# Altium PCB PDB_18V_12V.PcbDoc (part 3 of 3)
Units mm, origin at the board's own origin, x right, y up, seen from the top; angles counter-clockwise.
Board outline 185 x 160 mm, 4 copper layers (Top Layer, Int1 (GND), Int2 (GND), Bottom Layer), stack 1.636 mm thick; 209 components, 100 nets, 653 pads, 1413 vias.
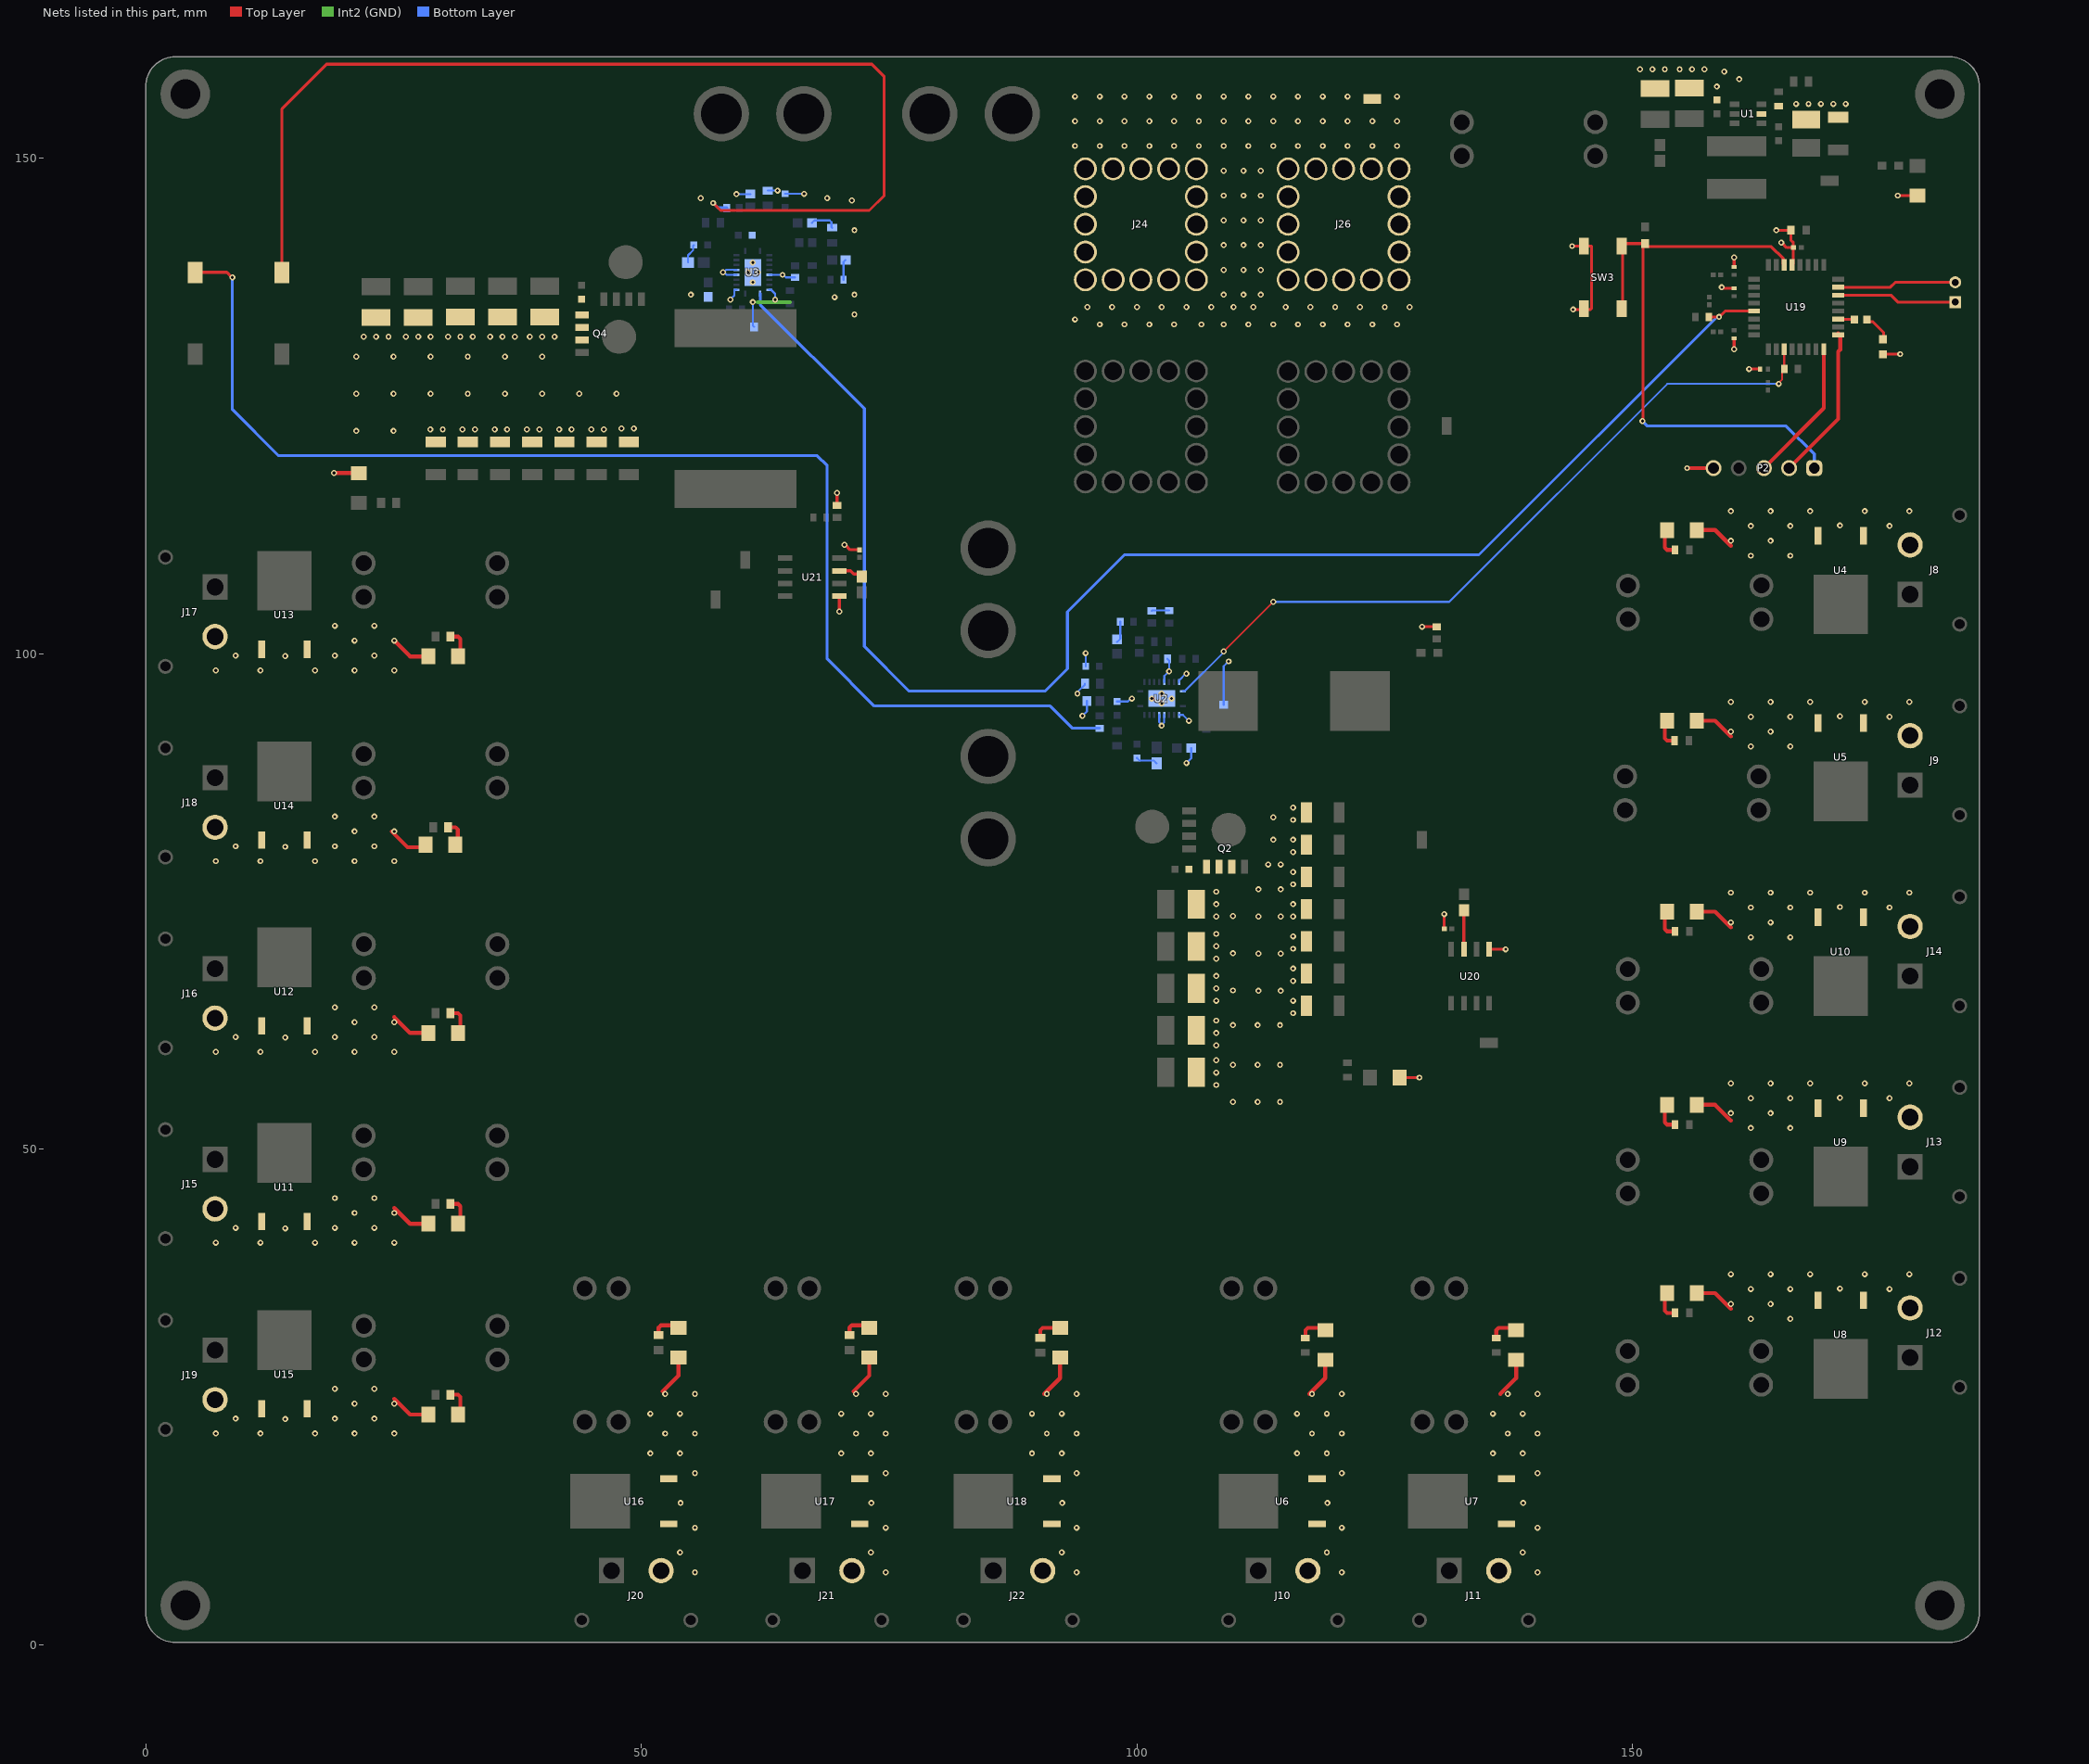
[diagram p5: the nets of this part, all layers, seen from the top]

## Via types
v1: diameter 0.6, hole 0.3, Top Layer to Bottom Layer, 1411 vias
v2: diameter 0.9, hole 0.4, Top Layer to Bottom Layer, 2 vias

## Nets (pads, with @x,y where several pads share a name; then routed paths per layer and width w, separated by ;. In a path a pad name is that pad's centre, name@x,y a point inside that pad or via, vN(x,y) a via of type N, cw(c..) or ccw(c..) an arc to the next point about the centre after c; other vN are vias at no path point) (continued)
GND: C3.2 C4.2 C5.1 C6.1 C7.1 C8.1 C9.1 C10.1 C11.1 C12.1 C13.1 C14.1 C15.2 C16.1 C19.2 C20.2 C21.2 C22.2 C23.2 C24.2 C25.2 C26.2 C29.1 C30.1 C31.1 C32.1 C33.1 C34.1 C35.1 C36.1 C37.1 C40.2 C42.2 C43.2 C44.2 C45.2 C46.2 C47.2 C48.2 C49.1 C50.1 C51.1 C52.1 C53.1 C54.1 C55.1 C56.1 D1.1 D2.1 D3.1 D4.1 D5.1 D6.1 D7.1 D8.1 D9.1 D10.1 D11.1 D12.1 D13.1 D14.1 D15.1 D16.1 D17.1 D18.1 D19.1 J2.1 J8.N J9.N J10.N J11.N J12.N J13.N J14.N J15.N J16.N J17.N J18.N J19.N J20.N J21.N J22.N J24.1 J24.2 J24.3 J24.4 J24.5 J24.6 J24.7 J24.8 J24.9 J24.10 J24.11 J24.12 J24.13 J24.14 J24.15 J24.16 J26.1 J26.2 J26.3 J26.4 J26.5 J26.6 J26.7 J26.8 J26.9 J26.10 J26.11 J26.12 J26.13 J26.14 J26.15 J26.16 P2.5 Q2.1 Q2.2 Q2.3 Q4.1 Q4.2 Q4.3 R7.2 R8.1 R9.2 R17.1 R21.2 R22.1 R30.1 R49.1 R50.1 SW3.1 SW3.2 U1.2 U2.6 U2.9 U2.12 U2.15 U2.16 U2.21 U3.6 U3.9 U3.12 U3.15 U3.16 U3.21 U4.1 U4.2 U5.1 U5.2 U6.1 U6.2 U7.1 U7.2 U8.1 U8.2 U9.1 U9.2 U10.1 U10.2 U11.1 U11.2 U12.1 U12.2 U13.1 U13.2 U14.1 U14.2 U15.1 U15.2 U16.1 U16.2 U17.1 U17.2 U18.1 U18.2 U19.5 U20.5 U21.5 | length 140.6
  Top Layer w0.3: R50.1@69.75,115 v1(69.75,116.25) ; v1(69.974,104.276) U21.5@69.974,105.845 ; v1(70.5,111) 70.575,111 71.068,110.507 C52.1@72,110.507 ; D2.1@126.5,57.25 v1(128.5,57.25) ; v1(128.769,102.75) R49.1@130.25,102.75 ; C51.1@131,72.25 v1(131,73.75) ; U20.5@135.52,70.198 v1(137.198,70.198) ; v1(143.9,141.15) 145.85,141.15 145.85,134.85 145.75,134.75 v1(144,134.75) ; v1(159,137) 159.1,136.9 C56.1@160.25,136.9 ; v1(160.25,130.75) C53.1@160.25,131.85 ; C54.1@160.25,139.05 v1(160.25,140) ; v1(161.75,128.75) C55.1@162.85,128.75 ; v1(164.5,142.75) C49.1@165.975,142.75 165.975,141.74 166.218,141.498 166.218,141.032 C50.1@166.25,141 ; v1(165,141.5) 165.042,141.5 165.542,141 C50.1@166.25,141 ; U19.5@166.1,139.25 166.2,139.35 166.2,140.95 C50.1@166.25,141 ; D19.1@175.25,130.25 v1(177,130.25) ; v1(176.75,146.25) D1.1@178.75,146.25
  Top Layer w0.4: v1(19,118.25) D3.1@21.5,118.25 ; v1@24.828,82.089 26.418,80.5 D14.1@28.25,80.5 ; 25.078,24.839 26.668,23.25 D15.1@28.5,23.25 ; 25.078,44.089 26.668,42.5 D11.1@28.5,42.5 ; 25.078,63.339 26.668,61.75 D12.1@28.5,61.75 ; v1(25.078,101.339) 26.668,99.75 D13.1@28.5,99.75 ; 52.161,25.578 53.75,27.168 D16.1@53.75,29 ; 71.411,25.578 73,27.168 D17.1@73,29 ; v1@90.661,25.328 92.25,26.918 D18.1@92.25,28.75 ; v1@117.411,25.328 119,26.918 D6.1@119,28.75 ; 136.661,25.328 138.25,26.918 D7.1@138.25,28.75 ; v1(155.5,118.75) P2.5@158.17,118.75 ; D8.1@156.5,35.5 158.332,35.5 159.922,33.911 ; D9.1@156.5,54.5 158.332,54.5 159.922,52.911 ; D10.1@156.5,74 158.332,74 159.922,72.411 ; D5.1@156.5,93.25 158.332,93.25 159.922,91.661 ; D4.1@156.5,112.5 158.332,112.5 159.922,110.911
  Int2 (GND) w0.4: 61.75,135.5 65,135.5
  Bottom Layer w0.2: v1(59,135.75) 59,135.799 59.4,136.199 59.4,136.73 59.42,136.75 U3.12@59.6,136.75 ; U3.15@59.6,138.25 58.608,138.25 58.358,138.5 v1(58.25,138.5) 58.293,138.5 58.543,138.75 U3.16@59.6,138.75 ; v1(59.6,146.4) R21.2@61,146.4 ; v1(61.25,135.5) 61.25,133.126 C40.2@61.376,133 ; R22.1@62.75,146.75 v1(63.75,146.75) ; U3.9@62.9,136.75 63.08,136.75 63.5,136.33 v1(63.5,135.75) ; U3.6@62.9,138.25 v1(64.25,138.25) 64.358,138.25 64.608,138 R30.1@65.5,138 ; C36.1@64.5,146.425 v1(66.425,146.425) ; v1(94,96) 94.077,96.077 94.077,96.227 94.75,96.9 R8.1@94.75,97 ; v1(94.5,93.75) 94.95,94.2 R7.2@94.95,95.25 ; C15.2@94.825,98.75 v1(94.825,100.075) ; C25.2@98,95.2 99.092,95.2 99.392,95.5 v1(99.5,95.5) ; U2.16@102.25,93.85 102.25,93.108 v1@102.5,92.858 ; v1(102.5,92.75) v1@102.5,92.858 ; U2.15@102.75,93.85 102.75,93.108 v1@102.5,92.858 ; U2.6@102.75,97.15 102.77,97.17 102.77,97.77 v1(103.25,98.25) 103.25,99.325 R17.1@103.075,99.5 ; U2.12@104.25,93.85 104.65,93.85 v1(105.25,93.25) ; U2.9@104.25,97.15 104.25,97.33 104.92,98 v1(105,98) ; v1(105,89) 105.477,89.477 C16.1@105.477,90.5 ; C26.2@108.75,94.876 108.75,98.76 109.24,99.25 v1(109.25,99.25)
  other v1: 55.411,7.328 74.661,7.328 93.911,7.328 120.661,7.328 140.411,7.328 53.911,9.328 73.161,9.328 92.411,9.328 119.161,9.328 138.911,9.328 55.411,11.828 74.661,11.828 93.911,11.828 120.661,11.828 140.411,11.828 53.96,14.328 73.21,14.328 92.46,14.328 119.21,14.328 138.96,14.328 55.411,17.328 74.661,17.328 93.911,17.328 120.661,17.328 140.411,17.328 50.911,19.328 53.911,19.328 70.161,19.328 73.161,19.328 89.411,19.328 92.411,19.328 116.161,19.328 119.161,19.328 135.911,19.328 138.911,19.328 7.078,21.339 11.578,21.339 17.078,21.339 21.078,21.339 25.078,21.339 52.411,21.328 55.411,21.328 71.661,21.328 74.661,21.328 90.911,21.328 93.911,21.328 117.661,21.328 120.661,21.328 137.411,21.328 140.411,21.328 14.078,22.79 9.078,22.839 19.078,22.839 23.078,22.839 50.911,23.328 53.911,23.328 70.161,23.328 73.161,23.328 89.411,23.328 92.411,23.328 116.161,23.328 119.161,23.328 135.911,23.328 138.911,23.328 21.078,24.339 25.078,24.339 52.411,25.328 55.411,25.328 71.661,25.328 74.661,25.328 90.911,25.328 93.911,25.328 117.661,25.328 120.661,25.328 137.411,25.328 140.411,25.328 19.078,25.839 23.078,25.839 161.922,32.911 165.922,32.911 159.922,34.411 163.922,34.411 161.922,35.911 165.922,35.911 175.922,35.911 170.922,35.96 159.922,37.411 163.922,37.411 167.922,37.411 173.422,37.411 177.922,37.411 7.078,40.589 11.578,40.589 17.078,40.589 21.078,40.589 25.078,40.589 14.078,42.04 9.078,42.089 19.078,42.089 23.078,42.089 21.078,43.589 25.078,43.589 19.078,45.089 23.078,45.089 161.922,52.161 165.922,52.161 159.922,53.661 163.922,53.661 109.685,54.788 112.185,54.788 114.435,54.788 161.922,55.161 165.922,55.161 175.922,55.161 170.922,55.21 108,56.5 159.922,56.661 163.922,56.661 167.922,56.661 173.422,56.661 177.922,56.661 108,57.75 109.685,58.538 112.185,58.538 114.435,58.538 108,59 7.078,59.839 11.578,59.839 17.078,59.839 21.078,59.839 25.078,59.839 108,60.5 14.078,61.29 9.078,61.339 19.078,61.339 23.078,61.339 108,61.75 109.685,62.538 112.185,62.538 114.435,62.538 21.078,62.839 25.078,62.839 108,63 115.75,63.75 19.078,64.339 23.078,64.339 108,65 115.75,65 112.25,66 114.5,66 109.685,66.038 108,66.25 115.75,67 108,67.5 115.75,68.25 108,69.25 112.25,69.75 114.5,69.75 109.685,69.788 115.75,70.25 108,70.5 161.922,71.411 165.922,71.411 115.75,71.5 108,71.75 159.922,72.911 163.922,72.911 108,73.5 112.25,73.5 114.5,73.5 115.75,73.5 109.685,73.538 161.922,74.411 165.922,74.411 175.922,74.411 170.922,74.46 108,74.75 115.75,74.75 159.922,75.911 163.922,75.911 167.922,75.911 173.422,75.911 177.922,75.911 108,76 112.25,76.25 114.5,76.25 115.75,76.75 115.75,78 113.25,78.75 114.5,78.75 7.078,79.089 11.578,79.089 17.078,79.089 21.078,79.089 25.078,79.089 115.75,80 14.078,80.54 9.078,80.589 19.078,80.589 23.078,80.589 113.75,81.25 115.75,81.25 21.078,82.089 25.078,82.089 115.75,83.25 113.75,83.5 19.078,83.589 23.078,83.589 115.75,84.5 161.922,90.661 165.922,90.661 159.922,92.161 163.922,92.161 161.922,93.661 165.922,93.661 175.922,93.661 170.922,93.71 102.5,95 159.922,95.161 163.922,95.161 167.922,95.161 173.422,95.161 177.922,95.161 101.5,95.5 103.5,95.5 102.5,96 7.078,98.339 11.578,98.339 17.078,98.339 21.078,98.339 25.078,98.339 14.078,99.79 9.078,99.839 19.078,99.839 23.078,99.839 21.078,101.339 19.078,102.839 23.078,102.839 161.922,109.911 165.922,109.911 159.922,111.411 163.922,111.411 161.922,112.911 165.922,112.911 175.922,112.911 170.922,112.96 159.922,114.411 163.922,114.411 167.922,114.411 173.422,114.411 177.922,114.411 21.25,122.5 25,122.5 28.717,122.651 29.967,122.651 31.967,122.651 33.217,122.651 35.217,122.651 36.467,122.651 38.467,122.651 39.717,122.651 41.717,122.651 42.967,122.651 44.967,122.651 46.217,122.651 48,122.75 49.25,122.75 21.25,126.25 25,126.25 28.75,126.25 32.5,126.25 36.25,126.25 40,126.25 43.75,126.25 47.5,126.25 21.25,130 25,130 28.75,130 32.5,130 36.25,130 40,130 22,132 23.25,132 24.5,132 26.25,132 27.5,132 28.75,132 30.5,132 31.75,132 33,132 34.75,132 36,132 37.25,132 38.75,132 40,132 41.25,132 96.25,133.25 98.75,133.25 101.25,133.25 103.75,133.25 106.5,133.25 108.75,133.25 111.25,133.25 113.75,133.25 116.25,133.25 118.75,133.25 121.25,133.25 123.75,133.25 126.25,133.25 93.75,133.75 71.5,134.25 95,135 97.5,135 100,135 102.5,135 105,135 107.5,135 109.75,135 111.75,135 115,135 117.5,135 120,135 122.5,135 125,135 127.5,135 69.5,136 55,136.25 71.5,136.25 108.75,136.25 110.75,136.25 112.5,136.25 61.25,137.5 60.75,138.5 61.75,138.5 108.75,138.75 110.75,138.75 112.5,138.75 61.25,139.5 108.75,141.25 110.75,141.25 112.5,141.25 71.5,142.75 108.75,143.75 110.75,143.75 112.5,143.75 71.25,145.75 56,146 68.75,146 108.75,146.25 110.75,146.25 112.5,146.25 108.75,148.75 110.75,148.75 112.5,148.75 93.75,151.25 96.25,151.25 98.75,151.25 101.25,151.25 103.75,151.25 106.25,151.25 108.75,151.25 111.25,151.25 113.75,151.25 116.25,151.25 118.75,151.25 121.25,151.25 123.75,151.25 126.25,151.25 93.75,153.75 96.25,153.75 98.75,153.75 101.25,153.75 103.75,153.75 106.25,153.75 108.75,153.75 111.25,153.75 113.75,153.75 116.25,153.75 118.75,153.75 121.25,153.75 123.75,153.75 126.25,153.75 166.5,155.5 167.75,155.5 169,155.5 170.25,155.5 171.5,155.5 93.75,156.25 96.25,156.25 98.75,156.25 101.25,156.25 103.75,156.25 106.25,156.25 108.75,156.25 111.25,156.25 113.75,156.25 116.25,156.25 118.75,156.25 121.25,156.25 126.25,156.25 158.5,157.25 160.75,158 159.25,158.75 150.75,159 152,159 153.25,159 154.75,159 156,159 157.25,159
LED_DEBUG_1: R46.1 U19.27 | length 1.6
  Top Layer w0.3: U19.27@170.75,133.8 170.775,133.775 172.348,133.775 R46.1@172.373,133.75
LED_DEBUG_2: D19.2 R46.2 | length 3
  Top Layer w0.3: R46.2@173.627,133.75 173.851,133.526 174.224,133.526 175.326,132.424 175.326,131.826 D19.2@175.25,131.75
MCU_NRST: P2.1 R53.1 SW3.3 SW3.4 U19.6 | length 61.2
  Top Layer w0.3: SW3.4@148.9,141.15 149.15,141.4 R53.1@151.25,141.4 ; SW3.3@149,135.172 SW3.4@149,140.5 ; v1(151,123.5) 151.057,123.557 151.057,141.1 R53.1@151.5,141.1 ; R53.1@151.25,141.35 151.409,141.191 R53.1@151.5,141.1 ; U19.6@165.3,139.25 165.2,139.35 165.2,139.895 163.995,141.1 R53.1@151.5,141.1
  Bottom Layer w0.3: v1(151,123.5) 151.5,123 165.5,123 168.33,120.17 P2.1@168.33,118.75
NetC2_1: C2.1 R4.2 | length 2.2
  Bottom Layer w0.2: C2.1@100,89.5 100.25,89.25 101.699,89.25 R4.2@102,88.949
NetC17_2: C17.2 R16.1 | length 2.2
  Bottom Layer w0.2: C17.2@98,101.202 98.323,101.525 R16.1@98.323,103.25
NetC18_2: C18.2 R13.2 | length 1.8
  Bottom Layer w0.2: C18.2@101.5,104.35 101.525,104.375 R13.2@103.25,104.375
NetC28_1: C28.1 R19.2 | length 2
  Bottom Layer w0.2: R19.2@54.699,139.5 54.712,139.513 54.712,140.212 55.217,140.717 55.217,141.167 C28.1@55.3,141.25
NetC38_2: C38.2 R27.1 | length 2.7
  Bottom Layer w0.2: C38.2@67.226,143.5 67.476,143.75 69,143.75 69.192,143.558 69.192,143.058 R27.1@69.25,143
NetC39_2: C39.2 R26.1 | length 2.1
  Bottom Layer w0.2: R26.1@70.4,137.75 70.4,139.546 C39.2@70.604,139.75
NetD4_2: D4.2 R31.1 | length 3
  Top Layer w0.4: D4.2@153.5,112.5 153.25,112.25 153.25,110.734 153.484,110.5 R31.1@154.25,110.5
NetD5_2: D5.2 R32.1 | length 3
  Top Layer w0.4: D5.2@153.5,93.25 153.25,93 153.25,91.484 153.484,91.25 R32.1@154.25,91.25
NetD6_2: D6.2 R33.1 | length 3
  Top Layer w0.4: R33.1@117,31 117,31.766 117.234,32 118.75,32 D6.2@119,31.75
NetD7_2: D7.2 R34.1 | length 3
  Top Layer w0.4: R34.1@136.25,31 136.25,31.766 136.484,32 138,32 D7.2@138.25,31.75
NetD8_2: D8.2 R35.1 | length 3
  Top Layer w0.4: D8.2@153.5,35.5 153.25,35.25 153.25,33.734 153.484,33.5 R35.1@154.25,33.5
NetD9_2: D9.2 R36.1 | length 3
  Top Layer w0.4: D9.2@153.5,54.5 153.25,54.25 153.25,52.734 153.484,52.5 R36.1@154.25,52.5
NetD10_2: D10.2 R37.1 | length 3
  Top Layer w0.4: D10.2@153.5,74 153.25,73.75 153.25,72.234 153.484,72 R37.1@154.25,72
NetD11_2: D11.2 R38.1 | length 3
  Top Layer w0.4: R38.1@30.75,44.5 31.516,44.5 31.75,44.266 31.75,42.75 D11.2@31.5,42.5
NetD12_2: D12.2 R39.1 | length 3
  Top Layer w0.4: R39.1@30.75,63.75 31.516,63.75 31.75,63.516 31.75,62 D12.2@31.5,61.75
NetD13_2: D13.2 R40.1 | length 3
  Top Layer w0.4: R40.1@30.75,101.75 31.516,101.75 31.75,101.516 31.75,100 D13.2@31.5,99.75
NetD14_2: D14.2 R41.1 | length 3
  Top Layer w0.4: R41.1@30.5,82.5 31.266,82.5 31.5,82.266 31.5,80.75 D14.2@31.25,80.5
NetD15_2: D15.2 R42.1 | length 3
  Top Layer w0.4: R42.1@30.75,25.25 31.516,25.25 31.75,25.016 31.75,23.5 D15.2@31.5,23.25
NetD16_2: D16.2 R43.1 | length 3
  Top Layer w0.4: R43.1@51.75,31.25 51.75,32.016 51.984,32.25 53.5,32.25 D16.2@53.75,32
NetD17_2: D17.2 R44.1 | length 3
  Top Layer w0.4: R44.1@71,31.25 71,32.016 71.234,32.25 72.75,32.25 D17.2@73,32
NetD18_2: D18.2 R45.1 | length 3
  Top Layer w0.4: R45.1@90.25,31 90.25,31.766 90.484,32 92,32 D18.2@92.25,31.75
NetR3_1: R3.1 SW1.2 | length 129.5
  Top Layer w0.3: SW1.2@5,138.492 5.008,138.5 8.189,138.5 8.689,138 v1(8.75,138)
  Bottom Layer w0.3: v1(8.75,138) 8.75,124.668 13.418,120 67.75,120 68.75,119 68.75,99.5 73.5,94.75 91.25,94.75 93.5,92.5 R3.1@96.25,92.5
NetR18_1: R18.1 SW2.2 | length 111.4
  Top Layer w0.3: SW2.2@13.75,138.492 13.75,155 18.25,159.5 73.25,159.5 74.5,158.25 74.5,146.25 73,144.75 58,144.75 v1(57.25,145.5)
  Bottom Layer w0.3: v1(57.25,145.5) 57.75,145 R18.1@58.625,145
NetR51_1: R51.1 U20.7 | length 4
  Top Layer w0.3: U20.7@132.98,70.198 132.98,74.128 R51.1@133,74.148
NetR52_1: R52.1 U21.7 | length 2.5
  Top Layer w0.3: U21.7@69.974,108.385 71.115,108.385 71.447,108.053 71.998,108.053 R52.1@72.25,107.801
PGOOD_12V: R24.1 U3.10 U19.13 | length 151.8
  Top Layer w0.3: R24.1@157.677,134 v1(158.722,134) ; v1@158.75,134 159.35,134.6 U19.13@162.25,134.6
  Bottom Layer w0.3: U3.10@62,136.35 62,135.25 72.5,124.75 72.5,100.75 77,96.25 90.75,96.25 93,98.5 93,104.25 98.75,110 134.5,110 158.443,133.943 158.665,133.943 v1(158.722,134)
PGOOD_18V: R11.1 U2.10 U19.19 | length 76.7
  Top Layer w0.2: v1(108.75,100.25) v1(113.75,105.25) ; v1(164.75,127.25) 164.75,127.358 165.094,127.702 165.094,128.521 R11.1@165.323,128.75 165.3,128.773 U19.19@165.3,130.75
  Bottom Layer w0.2: U2.10@104.65,96.25 104.67,96.27 104.85,96.27 108.75,100.17 v1(108.75,100.25) ; v1@113.83,105.25 131.5,105.25 153.5,127.25 v1(164.75,127.25)
SWD_SWCLK: P2.2 U19.25 | length 15.8
  Top Layer w0.4: P2.2@165.79,118.75 170.75,123.71 170.75,130.51 170.95,130.71 170.95,132.15 U19.25@170.75,132.35
SWD_SWDIO: P2.3 U19.24 | length 14.5
  Top Layer w0.4: P2.3@163.25,118.75 169.3,124.8 U19.24@169.3,130.75
UART_RX: P1.2 U19.31 | length 12
  Top Layer w0.3: U19.31@170.75,137 176,137 176.5,137.5 P1.2@182.55,137.5
UART_TX: P1.1 U19.30 | length 12.1
  Top Layer w0.3: U19.30@170.75,136.2 176.05,136.2 176.75,135.5 P1.1@182.55,135.5
pads on no net: J8.S1 J8.S2 J9.S1 J9.S2 J10.S1 J10.S2 J11.S1 J11.S2 J12.S1 J12.S2 J13.S1 J13.S2 J14.S1 J14.S2 J15.S1 J15.S2 J16.S1 J16.S2 J17.S1 J17.S2 J18.S1 J18.S2 J19.S1 J19.S2 J20.S1 J20.S2 J21.S1 J21.S2 J22.S1 J22.S2 U2.7 U3.7 U19.1 U19.2 U19.3 U19.7 U19.8 U19.10 U19.12 U19.14 U19.16 U19.18 U19.20 U19.21 U19.22 U19.23 U19.26 U19.28 U19.29 U19.32 U20.6 U21.6

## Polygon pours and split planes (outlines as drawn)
GND on Top Layer "GND_L02_P-001" (solid, remove dead copper, pour order 99): 105,77.25 104.75,77.5 104.75,79 105.25,79.5 112,79.5 112.75,80.25 112.75,85 113.25,85.5 118,85.5 118.5,85 118.5,53.75 117.25,52.5 106.25,52.5 105,53.75
24V_BUCK18 on Top Layer "GND_L02_P-001" (solid, remove dead copper, pour order 98): 77.5,93.75 91.25,93.75 92.5,92.5 92.5,86.25 93.75,85 103.5,85 104,84.5 104,79.25 104.25,79 104.25,53.75 103,52.5 77.5,52.5 76.25,53.75 76.25,92.5
B12V_SW on Top Layer "GND_L02_P-001" (solid, remove dead copper, pour order 90): 49.5,130 50.585,130.75 65.75,130.75 66,131 66,134.75 65.75,135 51.25,135 49.5,135
B12V_SW on Top Layer "GND_L02_P-001" (solid, remove dead copper, pour order 89): 45.5,136.25 46,136.75 49,136.75 49.5,136.25 49.5,135 49.923,134.577 50.247,134.577 50.247,130.057 50,129.75 49.75,129.75 45.75,129.75 45.5,130
GND on Top Layer "GND_L02_P-001" (solid, remove dead copper, pour order 88): 20.5,120.5 20,121 20,134 21.25,135.25 42.5,135.25 43.5,136.25 44.75,136.25 45,136 45,128.25 45.5,127.75 49.5,127.75 50.25,127 50.25,121 49.875,120.5
24V_BUCK12 on Top Layer "GND_L02_P-001" (solid, remove dead copper, pour order 86): 71.25,148.25 72.5,149.5 72.5,157.75 71.5,158.75 21.25,158.75 20,157.5 20,137 21.25,135.75 42.25,135.75 43.25,136.75 44.75,136.75 45.25,137.25 50.75,137.25 51.75,138.25 51.75,147 53,148.25
B18V_SW on Top Layer "GND_L02_P-001" (solid, remove dead copper, pour order 100): 104.75,79.75 104.5,80 104.5,83.25 104.75,83.5 106,83.5 106.25,83.75 106.25,84.75 106.5,85 112,85 112.25,84.75 112.25,80.25 111.75,79.75
12V on Top Layer "GND_L02_P-001" (solid, remove dead copper, pour order 94): 28.25,119 27.5,118.25 27.5,113.25 28.25,112.5 65.75,112.5 66.5,113.25 66.5,118.25 65.75,119
3.3V on Top Layer "GND_L02_P-001" (solid, remove dead copper, pour order 82): 165.75,152 166,152.25 173.25,152.25 173.5,152 173.5,145.5 173.25,145.25 156.75,145.25 156.5,145.5 156.5,148 156.75,148.25 165.5,148.25 165.75,148.5
18V_S on Top Layer "GND_L02_P-001" (solid, remove dead copper, pour order 107): 134,66 134.5,66.5 140,66.5 141,67.5 141,109 142,110 151.25,110 152.25,109 152.25,22.5 151,21.25 145,21.25 143.75,22.5 143.75,32.5 142.5,33.75 106.25,33.75 105,35 105,46.25 106.25,47.5 132.5,47.5 134,49
12V_S on Top Layer "GND_L02_P-001" (solid, remove dead copper, pour order 108): 42.5,107.5 41.25,108.75 41.25,110.25 40.25,111.25 33.5,111.25 32.5,110.25 32.5,26.25 33.75,25 37.5,25 40,27.5 40,32.5 41.25,33.75 92.5,33.75 93.75,35 93.75,46.25 92.5,47.5 68.25,47.5 66.5,49.25 66.5,107 66,107.5
B18V_SW on Top Layer "GND_L02_P-001" (solid, remove dead copper, pour order 101): 106.25,84.75 106.25,91.5 105.75,92 105.75,98.25 106.25,98.75 112,98.75 112.25,98.5 112.25,84.75
18V on Top Layer "GND_L02_P-001" (solid, remove dead copper, pour order 121): 129.75,60 132.75,60 133.25,60.5 133.25,66 132.75,66.5 129.75,66.5
18V on Top Layer "GND_L02_P-001" (solid, remove dead copper, pour order 102): 119.5,60.5 119.5,91.75 119,92.25 119,98.25 119.5,98.75 129.75,98.75 130.25,98.25 130.25,60.5 129.75,60 120,60
GND on Top Layer "GND_L02_P-001" (solid, remove dead copper, pour order 84): 93.75,132.5 92.5,133.75 92.5,157.5 93.75,158.75 127.5,158.75 128.75,157.5 128.75,133.75 127.5,132.5
24V on Top Layer "GND_L02_P-001" (solid, remove dead copper, pour order 83): 135,111.25 139.75,116 139.75,155 138.5,156.25 131.25,156.25 130,155 130,132.5 128.75,131.25 92.5,131.25 91.25,132.5 91.25,157.5 90,158.75 77.25,158.75 76.25,157.75 76.25,99.25 77.5,98 91.25,98 92.5,99.25 92.5,110 93.75,111.25
12V on Top Layer "GND_L02_P-001" (solid, remove dead copper, pour order 97): 51,108 46.5,112.5 65.75,112.5 66.5,113.25 66.5,108.5 66,108
GND on Top Layer "GND_L02_P-001" (solid, remove dead copper, pour order 79): 162.5,154.25 161.5,154.25 161.25,154.5 161.25,157.25 161,157.5 159.25,157.5 159,157.25 159,155.5 158.75,155.25 157.75,155.25 157,156 149.5,156 148.75,156.75 148.75,158.75 149.5,159.5 162,159.5 162.25,159.25 162.25,155 162.5,154.75 163.125,154.75
GND on Top Layer "GND_L02_P-001" (solid, remove dead copper, pour order 78): 162.5,154.25 165.5,154.25 165.75,154 165.75,153 166,152.75 173.25,152.75 173.5,153 173.5,155.5 173,156 164.5,156 164,155.5 164,155 163.75,154.75 162.5,154.75
3V3_SW on Top Layer "GND_L02_P-001" (solid, remove dead copper, pour order 76): 159.781,153.826 160.924,153.826 162.25,152.5 165,152.5 165.25,152.25 165.25,149.5 165,149.25 156.75,149.25 156.5,149.5 156.5,152 158.794,153.826
24V_BUCK on Top Layer "GND_L02_P-001" (solid, remove dead copper, pour order 74): 150.25,150 151,150.75 154.25,150.75 155,151.5 155,152.5 155.5,153 150.25,153 150.25,150.125
24V_BUCK on Top Layer "GND_L02_P-001" (solid, remove dead copper, pour order 72): 157.25,155 156.75,155.5 145,155.5 144.25,154.75 144.25,148 145,147.25 149.5,147.25 150.25,148 150.25,152.25 151,153 157.25,153 158.25,154 160.75,154 161,154.25 161,154.75 160.75,155
18V_Spare2 on Top Layer "GND_L02_P-001" (solid, remove dead copper, pour order 44): 134.161,5.828 133.161,4.828 125.661,4.828 124.661,5.828 124.661,25.828 125.661,26.828 133.161,26.828 134.161,25.828
18V_Spare1 on Top Layer "GND_L02_P-001" (solid, remove dead copper, pour order 40): 114.911,5.828 113.911,4.828 106.411,4.828 105.411,5.828 105.411,25.828 106.411,26.828 113.911,26.828 114.911,25.828
GND on Top Layer "GND_L02_P-001" (solid, remove dead copper, pour order 41): 115.411,25.828 116.411,26.828 121.411,26.828 122.411,25.828 122.411,5.828 121.577,4.828 116.411,4.828 115.411,5.828
GND on Top Layer "GND_L02_P-001" (solid, remove dead copper, pour order 45): 134.661,25.828 135.661,26.828 140.661,26.828 141.661,25.828 141.661,5.828 140.827,4.828 135.661,4.828 134.661,5.828
18V_NUC on Top Layer "GND_L02_P-001" (solid, remove dead copper, pour order 64): 179.422,108.661 180.422,107.661 180.422,100.161 179.422,99.161 159.422,99.161 158.422,100.161 158.422,107.661 159.422,108.661
18V_JETSON on Top Layer "GND_L02_P-001" (solid, remove dead copper, pour order 60): 179.422,89.411 180.422,88.411 180.422,80.911 179.422,79.911 159.422,79.911 158.422,80.911 158.422,88.411 159.422,89.411
18V_Spare3 on Top Layer "GND_L02_P-001" (solid, remove dead copper, pour order 48): 179.422,31.661 180.422,30.661 180.422,23.161 179.422,22.161 159.422,22.161 158.422,23.161 158.422,30.661 159.422,31.661
GND on Top Layer "GND_L02_P-001" (solid, remove dead copper, pour order 37): 88.661,25.828 89.661,26.828 94.661,26.828 95.661,25.828 95.661,5.828 94.827,4.828 89.661,4.828 88.661,5.828
GND on Top Layer "GND_L02_P-001" (solid, remove dead copper, pour order 21): 25.578,26.589 26.578,25.589 26.578,20.589 25.578,19.589 5.578,19.589 4.578,20.423 4.578,25.589 5.578,26.589
12V_Fans on Top Layer "GND_L02_P-001" (solid, remove dead copper, pour order 20): 5.578,27.089 4.578,28.089 4.578,35.589 5.578,36.589 25.578,36.589 26.578,35.589 26.578,28.089 25.578,27.089
GND on Top Layer "GND_L02_P-001" (solid, remove dead copper, pour order 17): 25.578,45.839 26.578,44.839 26.578,39.839 25.578,38.839 5.578,38.839 4.578,39.673 4.578,44.839 5.578,45.839
12V_USB_HUB on Top Layer "GND_L02_P-001" (solid, remove dead copper, pour order 16): 5.578,46.339 4.578,47.339 4.578,54.839 5.578,55.839 25.578,55.839 26.578,54.839 26.578,47.339 25.578,46.339
GND on Top Layer "GND_L02_P-001" (solid, remove dead copper, pour order 13): 25.578,65.089 26.578,64.089 26.578,59.089 25.578,58.089 5.578,58.089 4.578,58.923 4.578,64.089 5.578,65.089
12V_PTZ on Top Layer "GND_L02_P-001" (solid, remove dead copper, pour order 12): 5.578,65.589 4.578,66.589 4.578,74.089 5.578,75.089 25.578,75.089 26.578,74.089 26.578,66.589 25.578,65.589
GND on Top Layer "GND_L02_P-001" (solid, remove dead copper, pour order 9): 25.578,84.339 26.578,83.339 26.578,78.339 25.578,77.339 5.578,77.339 4.578,78.173 4.578,83.339 5.578,84.339
12V_RoverLab2 on Top Layer "GND_L02_P-001" (solid, remove dead copper, pour order 8): 5.578,84.839 4.578,85.839 4.578,93.339 5.578,94.339 25.578,94.339 26.578,93.339 26.578,85.839 25.578,84.839
GND on Top Layer "GND_L02_P-001" (solid, remove dead copper, pour order 1): 25.578,103.589 26.578,102.589 26.578,97.589 25.578,96.589 5.578,96.589 4.578,97.423 4.578,102.589 5.578,103.589
12V_RoverLab1 on Top Layer "GND_L02_P-001" (solid, remove dead copper, pour order 0): 5.578,104.089 4.578,105.089 4.578,112.589 5.578,113.589 25.578,113.589 26.578,112.589 26.578,105.089 25.578,104.089
GND on Top Layer "GND_L02_P-001" (solid, remove dead copper, pour order 49): 159.422,32.161 158.422,33.161 158.422,38.161 159.422,39.161 179.422,39.161 180.422,38.327 180.422,33.161 179.422,32.161
18V_Spare4 on Top Layer "GND_L02_P-001" (solid, remove dead copper, pour order 52): 179.422,50.911 180.422,49.911 180.422,42.411 179.422,41.411 159.422,41.411 158.422,42.411 158.422,49.911 159.422,50.911
GND on Top Layer "GND_L02_P-001" (solid, remove dead copper, pour order 53): 159.422,51.411 158.422,52.411 158.422,57.411 159.422,58.411 179.422,58.411 180.422,57.577 180.422,52.411 179.422,51.411
18V_Spare5 on Top Layer "GND_L02_P-001" (solid, remove dead copper, pour order 56): 179.422,70.161 180.422,69.161 180.422,61.661 179.422,60.661 159.422,60.661 158.422,61.661 158.422,69.161 159.422,70.161
GND on Top Layer "GND_L02_P-001" (solid, remove dead copper, pour order 57): 159.422,70.661 158.422,71.661 158.422,76.661 159.422,77.661 179.422,77.661 180.422,76.827 180.422,71.661 179.422,70.661
GND on Top Layer "GND_L02_P-001" (solid, remove dead copper, pour order 61): 159.422,89.911 158.422,90.911 158.422,95.911 159.422,96.911 179.422,96.911 180.422,96.077 180.422,90.911 179.422,89.911
GND on Top Layer "GND_L02_P-001" (solid, remove dead copper, pour order 65): 159.422,109.161 158.422,110.161 158.422,115.161 159.422,116.161 179.422,116.161 180.422,115.327 180.422,110.161 179.422,109.161
12V_Spare1 on Top Layer "GND_L02_P-001" (solid, remove dead copper, pour order 28): 49.661,5.828 48.661,4.828 41.161,4.828 40.161,5.828 40.161,25.828 41.161,26.828 48.661,26.828 49.661,25.828
GND on Top Layer "GND_L02_P-001" (solid, remove dead copper, pour order 29): 50.161,25.828 51.161,26.828 56.161,26.828 57.161,25.828 57.161,5.828 56.327,4.828 51.161,4.828 50.161,5.828
12V_Spare2 on Top Layer "GND_L02_P-001" (solid, remove dead copper, pour order 32): 68.911,5.828 67.911,4.828 60.411,4.828 59.411,5.828 59.411,25.828 60.411,26.828 67.911,26.828 68.911,25.828
GND on Top Layer "GND_L02_P-001" (solid, remove dead copper, pour order 33): 69.411,25.828 70.411,26.828 75.411,26.828 76.411,25.828 76.411,5.828 75.577,4.828 70.411,4.828 69.411,5.828
12V_Spare3 on Top Layer "GND_L02_P-001" (solid, remove dead copper, pour order 36): 88.161,5.828 87.161,4.828 79.661,4.828 78.661,5.828 78.661,25.828 79.661,26.828 87.161,26.828 88.161,25.828
24V_BUCK18 on Bottom Layer "GND_L02_P-001" (solid, remove dead copper, pour order 118): 77.5,93.75 91.25,93.75 92.5,92.5 92.5,86.25 93.75,85 103.5,85 104,84.5 104,79.25 104.25,79 104.25,53.75 103,52.5 77.5,52.5 76.25,53.75 76.25,92.5
24V_BUCK12 on Bottom Layer "GND_L02_P-001" (solid, remove dead copper, pour order 130): 71.25,148.25 72.5,149.5 72.5,157.75 71.5,158.75 21.25,158.75 20,157.5 20,137 21.25,135.75 42.25,135.75 43.25,136.75 44.75,136.75 45.25,137.25 50.75,137.25 51.75,138.25 51.75,147 53,148.25
24V on Bottom Layer "GND_L02_P-001" (solid, remove dead copper, pour order 129): 135,111.25 139.75,116 139.75,155 138.5,156.25 131.25,156.25 130,155 130,132.5 128.75,131.25 92.5,131.25 91.25,132.5 91.25,157.5 90,158.75 77.25,158.75 76.25,157.75 76.25,99.25 77.5,98 91.25,98 92.5,99.25 92.5,110 93.75,111.25
GND on Bottom Layer "GND_L02_P-001" (solid, remove dead copper, pour order 124): 55,132.5 53.75,133.75 53.75,146.25 55,147.5 71.25,147.5 72.5,146.25 72.5,133.75 71.25,132.5
GND on Bottom Layer "GND_L02_P-001" (solid, remove dead copper, pour order 128): 20.5,120.5 20,121 20,134 21.25,135.25 42.5,135.25 43.5,136.25 44.75,136.25 45,136 45,128.25 45.5,127.75 49.5,127.75 50.25,127 50.25,121 49.875,120.5
18V_Spare2 on Bottom Layer "GND_L02_P-001" (solid, remove dead copper, pour order 46): 134.161,5.828 133.161,4.828 125.661,4.828 124.661,5.828 124.661,25.828 125.661,26.828 133.161,26.828 134.161,25.828
GND on Bottom Layer "GND_L02_P-001" (solid, remove dead copper, pour order 127): 95,87.5 93.5,89 93.5,103.5 95,105 111.25,105 112.5,103.75 112.25,103.5 112.25,88.75 111,87.5
B18V_SW on Bottom Layer "GND_L02_P-001" (solid, remove dead copper, pour order 125): 104.75,79.75 104.5,80 104.5,83.25 104.75,83.5 106,83.5 106.25,83.75 106.25,84.75 106.5,85 112,85 112.25,84.75 112.25,80.25 111.75,79.75
GND on Bottom Layer "GND_L02_P-001" (solid, remove dead copper, pour order 119): 105,77.25 104.75,77.5 104.75,79 105.25,79.5 112,79.5 112.75,80.25 112.75,85 113.25,85.5 118,85.5 118.5,85 118.5,53.75 117.25,52.5 106.25,52.5 105,53.75
18V_S on Bottom Layer "GND_L02_P-001" (solid, remove dead copper, pour order 123): 134,66 134.5,66.5 140,66.5 141,67.5 141,109 142,110 151.25,110 152.25,109 152.25,22.5 151,21.25 145,21.25 143.75,22.5 143.75,32.5 142.5,33.75 106.25,33.75 105,35 105,46.25 106.25,47.5 132.5,47.5 134,49
12V_S on Bottom Layer "GND_L02_P-001" (solid, remove dead copper, pour order 122): 42.5,107.5 41.25,108.75 41.25,110.25 40.25,111.25 33.5,111.25 32.5,110.25 32.5,26.25 33.75,25 37.5,25 40,27.5 40,32.5 41.25,33.75 92.5,33.75 93.75,35 93.75,46.25 92.5,47.5 68.25,47.5 66.5,49.25 66.5,107 66,107.5
18V on Bottom Layer "GND_L02_P-001" (solid, remove dead copper, pour order 120): 119.5,60.5 119.5,91.75 119,92.25 119,98.25 119.5,98.75 129.75,98.75 130.25,98.25 130.25,60.5 129.75,60 120,60
18V on Bottom Layer "GND_L02_P-001" (solid, remove dead copper, pour order 104): 129.75,60 132.75,60 133.25,60.5 133.25,66 132.75,66.5 129.75,66.5
12V on Bottom Layer "GND_L02_P-001" (solid, remove dead copper, pour order 116): 51,108 46.5,112.5 65.75,112.5 66.5,113.25 66.5,108.5 66,108
12V on Bottom Layer "GND_L02_P-001" (solid, remove dead copper, pour order 115): 28.25,119 27.5,118.25 27.5,113.25 28.25,112.5 65.75,112.5 66.5,113.25 66.5,118.25 65.75,119
B12V_SW on Bottom Layer "GND_L02_P-001" (solid, remove dead copper, pour order 114): 45.5,136.25 46,136.75 49,136.75 49.5,136.25 49.5,135 49.923,134.577 50.247,134.577 50.247,130.057 50,129.75 49.75,129.75 45.75,129.75 45.5,130
GND on Bottom Layer "GND_L02_P-001" (solid, remove dead copper, pour order 109): 93.75,132.5 92.5,133.75 92.5,157.5 93.75,158.75 127.5,158.75 128.75,157.5 128.75,133.75 127.5,132.5
18V_Spare1 on Bottom Layer "GND_L02_P-001" (solid, remove dead copper, pour order 42): 114.911,5.828 113.911,4.828 106.411,4.828 105.411,5.828 105.411,25.828 106.411,26.828 113.911,26.828 114.911,25.828
GND on Bottom Layer "GND_L02_P-001" (solid, remove dead copper, pour order 43): 115.411,25.828 116.411,26.828 121.411,26.828 122.411,25.828 122.411,5.828 121.577,4.828 116.411,4.828 115.411,5.828
GND on Bottom Layer "GND_L02_P-001" (solid, remove dead copper, pour order 47): 134.661,25.828 135.661,26.828 140.661,26.828 141.661,25.828 141.661,5.828 140.827,4.828 135.661,4.828 134.661,5.828
18V_Spare5 on Bottom Layer "GND_L02_P-001" (solid, remove dead copper, pour order 58): 179.422,70.161 180.422,69.161 180.422,61.661 179.422,60.661 159.422,60.661 158.422,61.661 158.422,69.161 159.422,70.161
12V_Spare1 on Bottom Layer "GND_L02_P-001" (solid, remove dead copper, pour order 30): 49.661,5.828 48.661,4.828 41.161,4.828 40.161,5.828 40.161,25.828 41.161,26.828 48.661,26.828 49.661,25.828
GND on Bottom Layer "GND_L02_P-001" (solid, remove dead copper, pour order 3): 25.578,103.589 26.578,102.589 26.578,97.589 25.578,96.589 5.578,96.589 4.578,97.423 4.578,102.589 5.578,103.589
18V_Spare3 on Bottom Layer "GND_L02_P-001" (solid, remove dead copper, pour order 50): 179.422,31.661 180.422,30.661 180.422,23.161 179.422,22.161 159.422,22.161 158.422,23.161 158.422,30.661 159.422,31.661
GND on Bottom Layer "GND_L02_P-001" (solid, remove dead copper, pour order 51): 159.422,32.161 158.422,33.161 158.422,38.161 159.422,39.161 179.422,39.161 180.422,38.327 180.422,33.161 179.422,32.161
18V_Spare4 on Bottom Layer "GND_L02_P-001" (solid, remove dead copper, pour order 54): 179.422,50.911 180.422,49.911 180.422,42.411 179.422,41.411 159.422,41.411 158.422,42.411 158.422,49.911 159.422,50.911
GND on Bottom Layer "GND_L02_P-001" (solid, remove dead copper, pour order 55): 159.422,51.411 158.422,52.411 158.422,57.411 159.422,58.411 179.422,58.411 180.422,57.577 180.422,52.411 179.422,51.411
GND on Bottom Layer "GND_L02_P-001" (solid, remove dead copper, pour order 59): 159.422,70.661 158.422,71.661 158.422,76.661 159.422,77.661 179.422,77.661 180.422,76.827 180.422,71.661 179.422,70.661
18V_JETSON on Bottom Layer "GND_L02_P-001" (solid, remove dead copper, pour order 62): 179.422,89.411 180.422,88.411 180.422,80.911 179.422,79.911 159.422,79.911 158.422,80.911 158.422,88.411 159.422,89.411
GND on Bottom Layer "GND_L02_P-001" (solid, remove dead copper, pour order 63): 159.422,89.911 158.422,90.911 158.422,95.911 159.422,96.911 179.422,96.911 180.422,96.077 180.422,90.911 179.422,89.911
18V_NUC on Bottom Layer "GND_L02_P-001" (solid, remove dead copper, pour order 66): 179.422,108.661 180.422,107.661 180.422,100.161 179.422,99.161 159.422,99.161 158.422,100.161 158.422,107.661 159.422,108.661
GND on Bottom Layer "GND_L02_P-001" (solid, remove dead copper, pour order 67): 159.422,109.161 158.422,110.161 158.422,115.161 159.422,116.161 179.422,116.161 180.422,115.327 180.422,110.161 179.422,109.161
12V_RoverLab1 on Bottom Layer "GND_L02_P-001" (solid, remove dead copper, pour order 2): 5.578,104.089 4.578,105.089 4.578,112.589 5.578,113.589 25.578,113.589 26.578,112.589 26.578,105.089 25.578,104.089
12V_RoverLab2 on Bottom Layer "GND_L02_P-001" (solid, remove dead copper, pour order 10): 5.578,84.839 4.578,85.839 4.578,93.339 5.578,94.339 25.578,94.339 26.578,93.339 26.578,85.839 25.578,84.839
GND on Bottom Layer "GND_L02_P-001" (solid, remove dead copper, pour order 11): 25.578,84.339 26.578,83.339 26.578,78.339 25.578,77.339 5.578,77.339 4.578,78.173 4.578,83.339 5.578,84.339
12V_PTZ on Bottom Layer "GND_L02_P-001" (solid, remove dead copper, pour order 14): 5.578,65.589 4.578,66.589 4.578,74.089 5.578,75.089 25.578,75.089 26.578,74.089 26.578,66.589 25.578,65.589
GND on Bottom Layer "GND_L02_P-001" (solid, remove dead copper, pour order 15): 25.578,65.089 26.578,64.089 26.578,59.089 25.578,58.089 5.578,58.089 4.578,58.923 4.578,64.089 5.578,65.089
12V_USB_HUB on Bottom Layer "GND_L02_P-001" (solid, remove dead copper, pour order 18): 5.578,46.339 4.578,47.339 4.578,54.839 5.578,55.839 25.578,55.839 26.578,54.839 26.578,47.339 25.578,46.339
GND on Bottom Layer "GND_L02_P-001" (solid, remove dead copper, pour order 19): 25.578,45.839 26.578,44.839 26.578,39.839 25.578,38.839 5.578,38.839 4.578,39.673 4.578,44.839 5.578,45.839
12V_Fans on Bottom Layer "GND_L02_P-001" (solid, remove dead copper, pour order 22): 5.578,27.089 4.578,28.089 4.578,35.589 5.578,36.589 25.578,36.589 26.578,35.589 26.578,28.089 25.578,27.089
GND on Bottom Layer "GND_L02_P-001" (solid, remove dead copper, pour order 23): 25.578,26.589 26.578,25.589 26.578,20.589 25.578,19.589 5.578,19.589 4.578,20.423 4.578,25.589 5.578,26.589
GND on Bottom Layer "GND_L02_P-001" (solid, remove dead copper, pour order 31): 50.161,25.828 51.161,26.828 56.161,26.828 57.161,25.828 57.161,5.828 56.327,4.828 51.161,4.828 50.161,5.828
12V_Spare2 on Bottom Layer "GND_L02_P-001" (solid, remove dead copper, pour order 34): 68.911,5.828 67.911,4.828 60.411,4.828 59.411,5.828 59.411,25.828 60.411,26.828 67.911,26.828 68.911,25.828
GND on Bottom Layer "GND_L02_P-001" (solid, remove dead copper, pour order 35): 69.411,25.828 70.411,26.828 75.411,26.828 76.411,25.828 76.411,5.828 75.577,4.828 70.411,4.828 69.411,5.828
12V_Spare3 on Bottom Layer "GND_L02_P-001" (solid, remove dead copper, pour order 38): 88.161,5.828 87.161,4.828 79.661,4.828 78.661,5.828 78.661,25.828 79.661,26.828 87.161,26.828 88.161,25.828
GND on Bottom Layer "GND_L02_P-001" (solid, remove dead copper, pour order 39): 88.661,25.828 89.661,26.828 94.661,26.828 95.661,25.828 95.661,5.828 94.827,4.828 89.661,4.828 88.661,5.828
GND on Int2 (GND) "GND_L02_P-001" (solid, remove dead copper, pour order 69): 0,0.25 0,160.25 185,160.25 185,0.25
B18V_SW on Int2 (GND) "GND_L02_P-001" (solid, remove dead copper, pour order 126): 104.75,79.75 104.5,80 104.5,83.25 104.75,83.5 106,83.5 106.25,83.75 106.25,84.75 106.5,85 112,85 112.25,84.75 112.25,80.25 111.75,79.75
B12V_SW on Int2 (GND) "GND_L02_P-001" (solid, remove dead copper, pour order 113): 45.5,136.25 46,136.75 49,136.75 49.5,136.25 49.5,135 49.923,134.577 50.247,134.577 50.247,130.057 50,129.75 49.75,129.75 45.75,129.75 45.5,130
GND on Int1 (GND) "GND_L02_P-001" (solid, remove dead copper, pour order 71): 0,0.25 0,160.25 185,160.25 185,0.25

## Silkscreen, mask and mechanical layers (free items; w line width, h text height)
Top Overlay:
  drawing of 20 lines, arcs and shapes, not listed
  text "GND" at 104.302,154.287 h4 r180
  text "GND" at 124.302,154.287 h4 r180
  text "RX" at 179.7,139.8 h1 r270
  text "PDB1 UART" at 175.399,138.937 h2 r270
  text "TX" at 179.7,134.8 h1 r270
  text "NRST" at 149.975,132.717 h2 r180
  text "18V EN" at 8.113,127.956 h2 r180
  text "12V EN" at 17.113,127.956 h2 r180
  text "SWDIO" at 162.283,127.465 h2 r270
  text "SWCLK" at 164.783,127.465 h2 r270
  text "NRST" at 167.533,125.975 h2 r270
  text "GND" at 157.033,124.863 h2 r270
  text "3.3V" at 159.783,124.863 h2 r270
  text "18V" at 184.244,118.706 h3 r180
  text "24V VBAT" at 109.354,115.037 h4 r180
  text "24V VBAT" at 129.854,115.037 h4 r180
  text "+" at 1.254,111.171 h2
  text "+" at 183.445,101.601 h2 r180
  text "18V" at 184.238,99.366 h3 r180
  text "12V" at 6.25,97.179 h3 r180
  text "+" at 1.555,91.899 h2
  text "+" at 183.445,82.351 h2 r180
  text "18V" at 184.238,80.116 h3 r180
  text "12V" at 6.25,77.839 h3 r180
  text "+" at 1.504,72.671 h2
  text "+" at 183.445,63.101 h2 r180
  text "18V" at 184.238,60.866 h3 r180
  text "12V" at 6.75,58.545 h3 r180
  text "+" at 1.555,53.399 h2
  text "+" at 183.445,43.851 h2 r180
  text "18V" at 184.238,41.616 h3 r180
  text "12V" at 6.5,39.513 h3 r180
  text "+" at 1.555,34.149 h2
  text "+" at 182.305,22.649 h2
  text "12V" at 6.5,20.045 h3 r180
  text "Designed by: Rishi Upath & Lochlan Rode" at 38.779,9.374 h2 r180
  text "12V" at 56.705,6.75 h3 r270
  text "18V" at 121.955,6.75 h3 r270
  text "18V" at 141.205,6.75 h3 r270
  text "12V" at 75.955,6.5 h3 r270
  text "12V" at 95.205,6.5 h3 r270
  text "PDB2 | REV 1.0 | July 2026" at 38.779,6.264 h2.5 r180
  text "18V & 12V 20A PDB" at 38.779,3.751 h3 r180
  text "+" at 42.601,1.805 h2 r90
  text "+" at 61.851,1.805 h2 r90
  text "+" at 81.101,1.805 h2 r90
  text "+" at 107.851,1.805 h2 r90
  text "+" at 127.101,1.805 h2 r90
Mechanical 1:
  lines w0.254: 0,3.25 ccw(c3,3.25) 3,0.25 ; 0,3.25 0,157.25 cw(c3,157.25) 3,160.25 182,160.25 cw(c182,157.25) 185,157.25 185,3.25 cw(c182,3.25) 182,0.25 3,0.25 ; 0,3.25 0,3.25 ; 3,0.25 3,0.25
